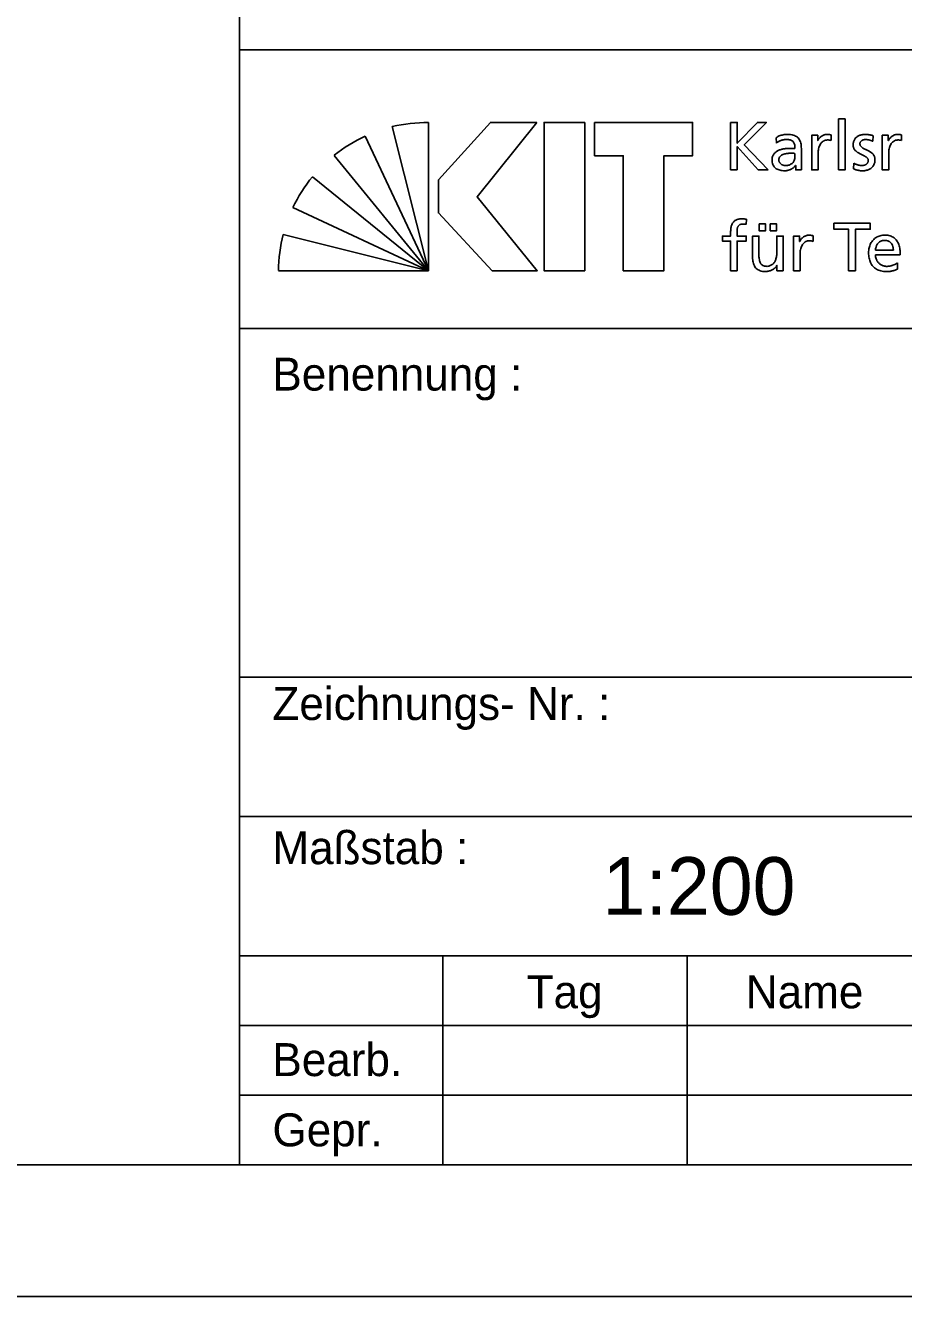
# Model space of a CAD drawing. Extents: x 0 to 84, y 0 to 59.4.
# Drawn here: x 63 to 73.67, y 0 to 15.43 of the extents above; entities that cross this region are included whole.
import ezdxf

# ---------------------------------------------------------------- set-up
doc = ezdxf.new("R2010")
doc.units = 0
doc.layers.add('90_Plankopf', color=7, linetype='Continuous')

msp = doc.modelspace()

# ---------------------------------------------------------------- linework, layer by layer
at = {"layer": '90_Plankopf'}
for p, q in [((65.6, 15.136), (65.6, 17.674)), ((65.6, 15.136), (82.4, 15.136)), ((67.455, 14.205), (67.896, 12.455)), ((67.896, 12.455), (67.896, 14.255)), ((71.562, 14.255), (71.562, 13.679)), ((67.896, 12.455), (67.127, 14.088)), ((72.116, 14.07), (72.12, 14.004)), ((72.785, 14.035), (72.785, 14.104)), ((73.292, 14.026), (73.298, 14.094)), ((73.642, 14.035), (73.642, 14.104)), ((72.424, 13.762), (72.424, 13.936)), ((66.749, 13.855), (67.896, 12.455)), ((72.346, 13.88), (72.346, 13.843)), ((73.06, 13.762), (73.056, 13.692)), ((67.896, 12.455), (66.487, 13.595)), ((71.562, 13.679), (71.645, 13.679)), ((71.901, 13.679), (72.022, 13.679)), ((66.248, 13.221), (67.896, 12.455)), ((71.755, 13.017), (71.758, 13.079)), ((67.896, 12.455), (66.132, 12.896)), ((72.566, 12.811), (72.566, 12.88)), ((73.541, 12.706), (73.323, 12.706)), ((73.323, 12.648), (73.624, 12.648)), ((73.592, 12.473), (73.592, 12.55)), ((66.073, 12.455), (67.896, 12.455)), ((65.6, 11.752), (82.4, 11.752)), ((65.6, 7.522), (82.4, 7.522)), ((65.6, 5.83), (82.4, 5.83)), ((65.6, 4.138), (82.4, 4.138)), ((65.6, 4.138), (82.4, 4.138)), ((65.6, 4.138), (82.4, 4.138)), ((65.6, 4.138), (82.4, 4.138)), ((65.6, 1.6), (65.6, 4.138)), ((68.071, 4.138), (68.071, 1.6)), ((71.036, 1.6), (71.036, 4.138)), ((65.6, 3.292), (74, 3.292)), ((65.6, 2.446), (74, 2.446)), ((65.6, 1.6), (82.4, 1.6)), ((65.6, 1.6), (82.4, 1.6))]:
    msp.add_line(p, q, dxfattribs=at)
for points in [[(0, 0), (84, 0), (84, 59.4), (0, 59.4)], [(1.6, 1.6), (82.4, 1.6), (82.4, 57.8), (1.6, 57.8)], [(69.213, 14.255), (68.647, 14.255), (68.015, 13.558), (68.015, 13.156), (68.668, 12.455), (69.217, 12.455), (68.485, 13.351)], [(69.794, 14.255), (69.794, 12.455), (69.3, 12.455), (69.3, 14.255)], [(69.913, 14.255), (69.913, 13.85), (70.26, 13.85), (70.26, 12.455), (70.754, 12.455), (70.754, 13.85), (71.102, 13.85), (71.102, 14.255)]]:
    msp.add_lwpolyline(points, close=True, dxfattribs=at)
for points in [[(65.6, 4.138), (65.6, 15.136)], [(72.022, 13.679), (71.73, 13.983), (72, 14.255), (71.891, 14.255), (71.645, 14.002), (71.645, 14.255), (71.562, 14.255)], [(72.876, 13.679), (72.954, 13.679), (72.954, 14.298), (72.876, 14.298), (72.876, 13.679)], [(72.625, 14.035), (72.623, 14.035), (72.623, 14.1), (72.55, 14.1), (72.55, 13.679), (72.628, 13.679), (72.628, 13.871)], [(73.482, 14.035), (73.48, 14.035), (73.48, 14.1), (73.407, 14.1), (73.407, 13.679), (73.485, 13.679), (73.485, 13.871)], [(71.645, 13.679), (71.645, 13.961), (71.901, 13.679)], [(72.353, 13.734), (72.355, 13.734), (72.355, 13.679), (72.427, 13.679)], [(71.911, 13.023), (71.911, 12.941), (71.989, 12.941), (71.989, 13.023), (71.911, 13.023)], [(72.046, 13.023), (72.046, 12.941), (72.124, 12.941), (72.124, 13.023), (72.046, 13.023)], [(72.998, 12.455), (73.081, 12.455), (73.081, 12.959), (73.26, 12.959), (73.26, 13.031), (72.819, 13.031), (72.819, 12.959), (72.998, 12.959), (72.998, 12.455)], [(71.565, 12.915), (71.565, 12.876), (71.466, 12.876), (71.466, 12.814), (71.565, 12.814), (71.565, 12.455), (71.643, 12.455), (71.643, 12.814), (71.754, 12.814), (71.754, 12.876), (71.643, 12.876), (71.643, 12.922)], [(71.909, 12.658), (71.909, 12.876), (71.831, 12.876), (71.831, 12.626)], [(72.203, 12.455), (72.203, 12.876), (72.126, 12.876), (72.126, 12.681)], [(72.405, 12.811), (72.403, 12.811), (72.403, 12.876), (72.33, 12.876), (72.33, 12.455), (72.408, 12.455), (72.408, 12.647)], [(72.126, 12.522), (72.128, 12.522), (72.128, 12.455), (72.203, 12.455)], [(82.4, 4.138), (65.6, 4.138)], [(65.6, 4.138), (65.6, 4.138)], [(65.6, 1.6), (82.4, 1.6)]]:
    msp.add_lwpolyline(points, dxfattribs=at)
for centre, start, end in [((67.89, 12.349), 89.8053, 103.1895), ((67.933, 12.362), 115.0126, 128.3968), ((67.963, 12.391), 140.7898, 154.174), ((67.978, 12.426), 165.7222, 179.1064)]:
    msp.add_arc(centre, 1.906, start, end, dxfattribs=at)
for points in [[(72.424, 13.936), (72.424, 13.974), (72.418, 14.006), (72.407, 14.032), (72.395, 14.058), (72.377, 14.077), (72.352, 14.09), (72.327, 14.103), (72.295, 14.11), (72.255, 14.11), (72.228, 14.11), (72.203, 14.106), (72.18, 14.099), (72.157, 14.092), (72.135, 14.082), (72.116, 14.07)], [(72.12, 14.004), (72.131, 14.013), (72.143, 14.021), (72.156, 14.027), (72.169, 14.034), (72.183, 14.039), (72.198, 14.042), (72.213, 14.046), (72.228, 14.047), (72.242, 14.047), (72.268, 14.047), (72.288, 14.043), (72.304, 14.035), (72.319, 14.027), (72.33, 14.015), (72.337, 13.998), (72.343, 13.982), (72.346, 13.962), (72.346, 13.937)], [(72.785, 14.104), (72.78, 14.105), (72.775, 14.106), (72.77, 14.107), (72.765, 14.108), (72.76, 14.109), (72.754, 14.109), (72.748, 14.11), (72.742, 14.11), (72.734, 14.11), (72.719, 14.11), (72.705, 14.107), (72.691, 14.1), (72.677, 14.094), (72.664, 14.085), (72.652, 14.074), (72.641, 14.063), (72.632, 14.05), (72.625, 14.035)], [(73.298, 14.094), (73.283, 14.098), (73.268, 14.102), (73.252, 14.105), (73.236, 14.108), (73.22, 14.11), (73.202, 14.11), (73.181, 14.11), (73.161, 14.107), (73.143, 14.102), (73.125, 14.097), (73.11, 14.089), (73.096, 14.078), (73.083, 14.067), (73.072, 14.054), (73.065, 14.038), (73.057, 14.021), (73.053, 14.002), (73.053, 13.98), (73.053, 13.964), (73.057, 13.949), (73.063, 13.937), (73.07, 13.925), (73.078, 13.914), (73.089, 13.905), (73.1, 13.896), (73.112, 13.888), (73.125, 13.881), (73.138, 13.874), (73.151, 13.867), (73.164, 13.861), (73.177, 13.855), (73.189, 13.849), (73.199, 13.842), (73.21, 13.836), (73.219, 13.829), (73.225, 13.821), (73.232, 13.813), (73.235, 13.803), (73.235, 13.792), (73.235, 13.781), (73.233, 13.771), (73.228, 13.764), (73.223, 13.756), (73.217, 13.75), (73.209, 13.745), (73.201, 13.74), (73.193, 13.737), (73.184, 13.735), (73.174, 13.733), (73.165, 13.732), (73.156, 13.732), (73.149, 13.732), (73.139, 13.733), (73.128, 13.735), (73.117, 13.737), (73.105, 13.741), (73.093, 13.745), (73.081, 13.75), (73.07, 13.755), (73.06, 13.762)], [(73.056, 13.692), (73.073, 13.683), (73.092, 13.677), (73.112, 13.674), (73.131, 13.67), (73.151, 13.669), (73.171, 13.669), (73.19, 13.669), (73.208, 13.672), (73.226, 13.677), (73.243, 13.682), (73.259, 13.69), (73.273, 13.701), (73.286, 13.712), (73.298, 13.726), (73.306, 13.742), (73.314, 13.759), (73.318, 13.778), (73.318, 13.8), (73.318, 13.82), (73.314, 13.836), (73.308, 13.849), (73.301, 13.862), (73.293, 13.874), (73.282, 13.883), (73.271, 13.892), (73.259, 13.9), (73.246, 13.907), (73.233, 13.914), (73.22, 13.92), (73.207, 13.925), (73.194, 13.931), (73.183, 13.937), (73.172, 13.943), (73.161, 13.95), (73.152, 13.957), (73.146, 13.965), (73.139, 13.974), (73.136, 13.984), (73.136, 13.996), (73.136, 14.008), (73.139, 14.017), (73.146, 14.025), (73.153, 14.032), (73.162, 14.038), (73.173, 14.042), (73.184, 14.046), (73.197, 14.047), (73.21, 14.047), (73.215, 14.047), (73.221, 14.047), (73.228, 14.046), (73.235, 14.044), (73.243, 14.043), (73.251, 14.041), (73.259, 14.039), (73.267, 14.036), (73.274, 14.034), (73.281, 14.031), (73.287, 14.029), (73.292, 14.026)], [(73.642, 14.104), (73.637, 14.105), (73.632, 14.106), (73.627, 14.107), (73.622, 14.108), (73.617, 14.109), (73.611, 14.109), (73.605, 14.11), (73.599, 14.11), (73.591, 14.11), (73.576, 14.11), (73.562, 14.107), (73.548, 14.1), (73.534, 14.094), (73.521, 14.085), (73.509, 14.074), (73.498, 14.063), (73.489, 14.05), (73.482, 14.035)], [(72.346, 13.937), (72.336, 13.938), (72.327, 13.938), (72.318, 13.939), (72.309, 13.939), (72.301, 13.939), (72.292, 13.939), (72.283, 13.939), (72.274, 13.939), (72.264, 13.939), (72.248, 13.939), (72.23, 13.938), (72.213, 13.935), (72.195, 13.932), (72.177, 13.927), (72.16, 13.921), (72.143, 13.914), (72.128, 13.906), (72.114, 13.895), (72.1, 13.884), (72.089, 13.871), (72.081, 13.856), (72.073, 13.84), (72.068, 13.822), (72.068, 13.8), (72.068, 13.77), (72.075, 13.745), (72.088, 13.726), (72.101, 13.706), (72.119, 13.692), (72.142, 13.683), (72.165, 13.674), (72.192, 13.669), (72.222, 13.669), (72.24, 13.669), (72.256, 13.672), (72.27, 13.676), (72.284, 13.68), (72.297, 13.685), (72.307, 13.692), (72.318, 13.698), (72.327, 13.705), (72.335, 13.713), (72.342, 13.72), (72.348, 13.727), (72.353, 13.734)], [(72.628, 13.871), (72.628, 13.906), (72.633, 13.937), (72.642, 13.962), (72.652, 13.988), (72.665, 14.008), (72.682, 14.021), (72.699, 14.035), (72.719, 14.042), (72.743, 14.042), (72.749, 14.042), (72.756, 14.042), (72.764, 14.041), (72.771, 14.04), (72.778, 14.038), (72.785, 14.035)], [(73.485, 13.871), (73.485, 13.906), (73.49, 13.937), (73.499, 13.962), (73.509, 13.988), (73.522, 14.008), (73.539, 14.021), (73.556, 14.035), (73.576, 14.042), (73.6, 14.042), (73.606, 14.042), (73.613, 14.042), (73.621, 14.041), (73.628, 14.04), (73.635, 14.038), (73.642, 14.035)], [(72.346, 13.843), (72.346, 13.822), (72.342, 13.803), (72.333, 13.786), (72.324, 13.769), (72.311, 13.756), (72.294, 13.747), (72.276, 13.737), (72.255, 13.732), (72.229, 13.732), (72.22, 13.732), (72.211, 13.734), (72.202, 13.736), (72.193, 13.739), (72.184, 13.744), (72.177, 13.749), (72.169, 13.755), (72.163, 13.763), (72.158, 13.771), (72.153, 13.779), (72.151, 13.789), (72.151, 13.8), (72.151, 13.815), (72.155, 13.828), (72.162, 13.837), (72.169, 13.847), (72.178, 13.855), (72.19, 13.861), (72.202, 13.867), (72.214, 13.871), (72.227, 13.874), (72.24, 13.877), (72.253, 13.879), (72.265, 13.88), (72.278, 13.881), (72.288, 13.881), (72.297, 13.881), (72.305, 13.881), (72.313, 13.881), (72.322, 13.881), (72.33, 13.88), (72.338, 13.88), (72.346, 13.88)], [(72.427, 13.679), (72.427, 13.683), (72.426, 13.689), (72.425, 13.695), (72.425, 13.702), (72.425, 13.711), (72.424, 13.722), (72.424, 13.733), (72.424, 13.746), (72.424, 13.762)], [(71.758, 13.079), (71.75, 13.08), (71.742, 13.082), (71.734, 13.083), (71.725, 13.084), (71.716, 13.084), (71.706, 13.084), (71.678, 13.084), (71.654, 13.08), (71.636, 13.072), (71.617, 13.064), (71.603, 13.053), (71.593, 13.038), (71.582, 13.023), (71.575, 13.005), (71.571, 12.985), (71.567, 12.964), (71.565, 12.941), (71.565, 12.915)], [(71.643, 12.922), (71.643, 12.936), (71.643, 12.949), (71.645, 12.961), (71.647, 12.973), (71.65, 12.984), (71.655, 12.993), (71.66, 13.002), (71.668, 13.009), (71.678, 13.014), (71.688, 13.019), (71.701, 13.021), (71.718, 13.021), (71.724, 13.021), (71.731, 13.021), (71.738, 13.02), (71.745, 13.019), (71.75, 13.018), (71.755, 13.017)], [(72.566, 12.88), (72.56, 12.881), (72.555, 12.882), (72.55, 12.883), (72.545, 12.884), (72.54, 12.885), (72.534, 12.885), (72.529, 12.886), (72.522, 12.886), (72.514, 12.886), (72.499, 12.886), (72.485, 12.883), (72.471, 12.876), (72.457, 12.87), (72.444, 12.861), (72.432, 12.85), (72.421, 12.839), (72.412, 12.826), (72.405, 12.811)], [(72.408, 12.647), (72.408, 12.682), (72.413, 12.713), (72.422, 12.738), (72.432, 12.764), (72.445, 12.784), (72.462, 12.797), (72.479, 12.811), (72.499, 12.818), (72.523, 12.818), (72.529, 12.819), (72.536, 12.818), (72.544, 12.817), (72.551, 12.816), (72.558, 12.814), (72.566, 12.811)], [(73.624, 12.648), (73.624, 12.682), (73.621, 12.714), (73.615, 12.743), (73.608, 12.772), (73.598, 12.797), (73.584, 12.818), (73.569, 12.839), (73.55, 12.856), (73.526, 12.868), (73.503, 12.88), (73.473, 12.886), (73.438, 12.886), (73.408, 12.886), (73.381, 12.881), (73.357, 12.87), (73.333, 12.86), (73.312, 12.845), (73.295, 12.826), (73.278, 12.807), (73.264, 12.785), (73.255, 12.759), (73.246, 12.733), (73.241, 12.705), (73.241, 12.673), (73.241, 12.639), (73.245, 12.608), (73.254, 12.58), (73.263, 12.552), (73.276, 12.528), (73.294, 12.508), (73.312, 12.488), (73.334, 12.472), (73.362, 12.462), (73.389, 12.451), (73.422, 12.446), (73.459, 12.445), (73.482, 12.446), (73.501, 12.447), (73.518, 12.45), (73.534, 12.453), (73.548, 12.457), (73.56, 12.461), (73.571, 12.465), (73.582, 12.469), (73.592, 12.473)], [(73.323, 12.706), (73.325, 12.72), (73.328, 12.734), (73.333, 12.747), (73.338, 12.761), (73.345, 12.774), (73.354, 12.785), (73.363, 12.797), (73.374, 12.806), (73.388, 12.813), (73.401, 12.82), (73.418, 12.823), (73.437, 12.823), (73.453, 12.823), (73.468, 12.82), (73.481, 12.814), (73.494, 12.808), (73.505, 12.8), (73.514, 12.789), (73.523, 12.778), (73.53, 12.766), (73.534, 12.752), (73.539, 12.738), (73.541, 12.722), (73.541, 12.706)], [(72.126, 12.681), (72.126, 12.656), (72.123, 12.632), (72.118, 12.611), (72.113, 12.59), (72.105, 12.572), (72.095, 12.556), (72.084, 12.541), (72.071, 12.529), (72.055, 12.521), (72.039, 12.512), (72.02, 12.508), (71.998, 12.508), (71.975, 12.509), (71.957, 12.516), (71.944, 12.527), (71.931, 12.538), (71.922, 12.555), (71.917, 12.577), (71.911, 12.598), (71.908, 12.626), (71.909, 12.658)], [(71.831, 12.626), (71.831, 12.588), (71.836, 12.556), (71.848, 12.529), (71.859, 12.502), (71.876, 12.481), (71.899, 12.467), (71.923, 12.453), (71.952, 12.446), (71.989, 12.445), (72.008, 12.446), (72.027, 12.449), (72.045, 12.455), (72.063, 12.461), (72.079, 12.47), (72.093, 12.481), (72.108, 12.492), (72.119, 12.506), (72.126, 12.522)], [(73.592, 12.55), (73.587, 12.546), (73.58, 12.542), (73.571, 12.537), (73.561, 12.532), (73.551, 12.528), (73.539, 12.523), (73.527, 12.519), (73.515, 12.515), (73.501, 12.512), (73.488, 12.51), (73.475, 12.508), (73.462, 12.508), (73.444, 12.508), (73.426, 12.512), (73.409, 12.518), (73.393, 12.525), (73.378, 12.535), (73.365, 12.547), (73.352, 12.559), (73.342, 12.574), (73.335, 12.591), (73.327, 12.609), (73.324, 12.628), (73.323, 12.648)]]:
    msp.add_open_spline(points, degree=3, dxfattribs=at)

# ---------------------------------------------------------------- texts
for s, height, p in [('Benennung :', 0.4, (66, 11)), ('Zeichnungs- Nr. :', 0.4, (66, 7)), ('Maßstab :', 0.4, (66, 5.25)), ('1:200   ', 0.7, (70.01, 4.635)), ('Tag', 0.4, (69.088, 3.5)), ('Name', 0.4, (71.75, 3.5)), ('Bearb.', 0.4, (66, 2.677)), ('Gepr.', 0.4, (66, 1.824))]:
    msp.add_text(s, height=height, dxfattribs=at).set_placement(p)

doc.saveas('drawing.dxf')
